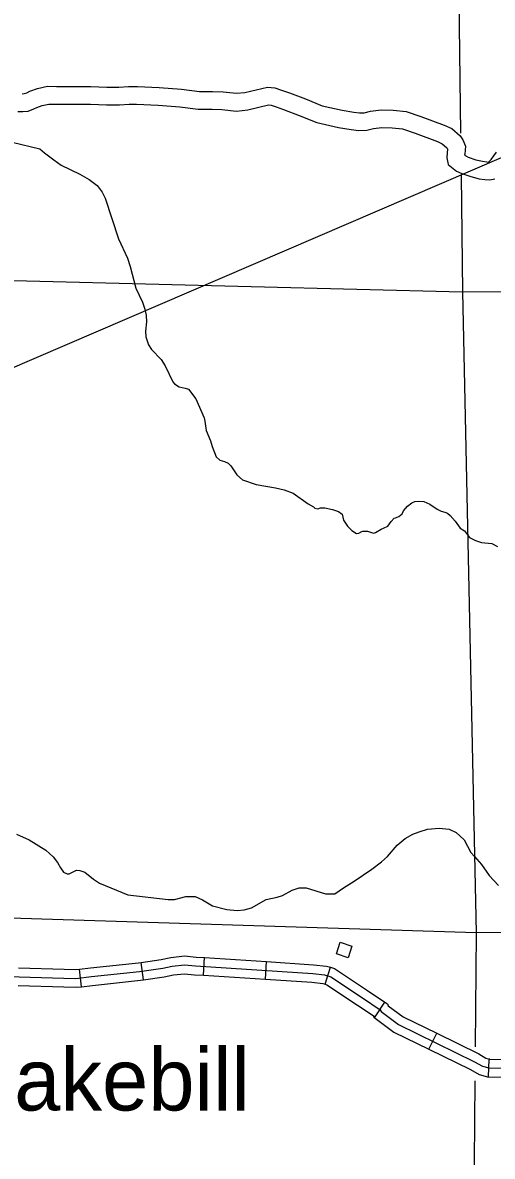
# Model space of a CAD drawing. Extents: x 1369885 to 1370219, y 379980 to 380218.
# Drawn here: x 1370011.52 to 1370027.38, y 380056.29 to 380094.55 of the extents above; entities that cross this region are included whole.
import ezdxf

# ---------------------------------------------------------------- set-up
doc = ezdxf.new("R2010")
doc.units = 0
for name, color, linetype in [('Level 24', 7, 'Continuous'), ('Level 32', 7, 'Continuous'), ('Level 35', 7, 'Continuous'), ('Level 46', 7, 'Continuous'), ('Level 5', 7, 'Continuous'), ('Level 56', 7, 'Continuous'), ('Page Text', 7, 'Continuous')]:
    doc.layers.add(name, color=color, linetype=linetype)

msp = doc.modelspace()

# ---------------------------------------------------------------- linework, layer by layer
at = {"layer": 'Level 32'}
for p, q in [((1370015.603, 380062.251), (1370015.519, 380062.841)), ((1370017.623, 380062.403), (1370017.661, 380062.999)), ((1370019.719, 380062.269), (1370019.757, 380062.864)), ((1370013.507, 380062.02), (1370013.44, 380062.613)), ((1370021.741, 380062.102), (1370021.915, 380062.673)), ((1370023.422, 380061.001), (1370023.754, 380061.496)), ((1370025.239, 380059.91), (1370025.502, 380060.446)), ((1370027.257, 380058.981), (1370027.269, 380059.577))]:
    msp.add_line(p, q, dxfattribs=at)
for points in [[(1370013.44, 380062.613), (1370013.813, 380062.655), (1370015.429, 380062.829), (1370015.519, 380062.841)], [(1370015.519, 380062.841), (1370016.197, 380062.937), (1370016.521, 380063.005), (1370016.988, 380063.057), (1370017.378, 380063.017), (1370017.661, 380062.999)], [(1370017.661, 380062.999), (1370019.757, 380062.864)], [(1370019.757, 380062.864), (1370021.341, 380062.762), (1370021.78, 380062.714), (1370021.915, 380062.673)], [(1370011.018, 380062.364), (1370012.915, 380062.308), (1370013.317, 380062.299), (1370013.846, 380062.359), (1370015.466, 380062.533), (1370016.249, 380062.643)], [(1370011.384, 380062.652), (1370012.923, 380062.606), (1370013.304, 380062.598), (1370013.44, 380062.613)], [(1370015.603, 380062.251), (1370016.3, 380062.349), (1370016.616, 380062.415), (1370016.99, 380062.457), (1370017.329, 380062.422), (1370017.623, 380062.403)], [(1370016.249, 380062.643), (1370016.569, 380062.71), (1370016.989, 380062.757), (1370017.353, 380062.72), (1370021.315, 380062.465), (1370021.719, 380062.42), (1370021.926, 380062.357), (1370022.997, 380061.646), (1370023.599, 380061.241), (1370023.626, 380061.178), (1370024.211, 380060.746), (1370026.784, 380059.486), (1370027.053, 380059.333), (1370027.26, 380059.279), (1370029.202, 380059.241), (1370030.244, 380059.213), (1370032.987, 380059.233), (1370034.444, 380059.287), (1370034.646, 380059.278)], [(1370021.915, 380062.673), (1370022.055, 380062.63), (1370023.162, 380061.894), (1370023.754, 380061.496)], [(1370013.507, 380062.02), (1370013.879, 380062.062), (1370015.503, 380062.236), (1370015.603, 380062.251)], [(1370017.623, 380062.403), (1370019.719, 380062.269)], [(1370019.719, 380062.269), (1370021.289, 380062.168), (1370021.659, 380062.127), (1370021.741, 380062.102)], [(1370021.741, 380062.102), (1370021.798, 380062.084), (1370022.831, 380061.398), (1370023.422, 380061.001)], [(1370011.366, 380062.056), (1370012.907, 380062.01), (1370013.33, 380062), (1370013.507, 380062.02)], [(1370023.754, 380061.496), (1370023.839, 380061.439), (1370023.869, 380061.37), (1370024.367, 380061.002), (1370025.502, 380060.446)], [(1370023.36, 380061.043), (1370023.384, 380060.986), (1370024.055, 380060.49), (1370025.239, 380059.91)], [(1370025.502, 380060.446), (1370026.923, 380059.75), (1370027.167, 380059.612), (1370027.301, 380059.576), (1370027.269, 380059.577)], [(1370025.239, 380059.91), (1370026.644, 380059.222), (1370026.94, 380059.054), (1370027.219, 380058.981), (1370027.257, 380058.981)], [(1370027.269, 380059.577), (1370029.209, 380059.54), (1370029.371, 380059.535)], [(1370027.257, 380058.981), (1370029.195, 380058.943), (1370029.355, 380058.939)]]:
    msp.add_lwpolyline(points, dxfattribs=at)
at = {"layer": 'Level 35'}
for points in [[(1370011.164, 380090.524), (1370012.097, 380090.293), (1370012.26, 380090.155), (1370012.572, 380089.92), (1370012.819, 380089.748), (1370013.452, 380089.441), (1370013.764, 380089.255), (1370014.032, 380089.06), (1370014.202, 380088.826), (1370014.303, 380088.633), (1370014.762, 380087.256), (1370015.056, 380086.607), (1370015.156, 380086.319), (1370015.345, 380085.592), (1370015.57, 380085.12), (1370015.648, 380084.879), (1370015.691, 380084.669), (1370015.705, 380084.451), (1370015.667, 380084.139), (1370015.685, 380083.944), (1370015.768, 380083.679), (1370015.872, 380083.519), (1370016.193, 380083.182), (1370016.338, 380082.975), (1370016.593, 380082.433), (1370016.647, 380082.359), (1370016.805, 380082.26), (1370017.008, 380082.222), (1370017.117, 380082.178), (1370017.369, 380081.862), (1370017.651, 380081.213), (1370017.678, 380081.102)], [(1370017.678, 380081.102), (1370017.719, 380080.785), (1370017.865, 380080.438), (1370017.918, 380080.245), (1370018.052, 380079.898), (1370018.183, 380079.786), (1370018.335, 380079.747), (1370018.456, 380079.691), (1370018.554, 380079.594), (1370018.754, 380079.297), (1370018.946, 380079.12), (1370019.403, 380078.97), (1370020.054, 380078.856), (1370020.349, 380078.785), (1370020.655, 380078.673), (1370021.158, 380078.317), (1370021.341, 380078.21), (1370021.391, 380078.169), (1370021.493, 380078.149), (1370021.575, 380078.174), (1370021.722, 380078.174), (1370021.981, 380078.123), (1370022.185, 380078.052), (1370022.307, 380077.966), (1370022.358, 380077.762), (1370022.49, 380077.558), (1370022.632, 380077.411), (1370022.79, 380077.309), (1370022.876, 380077.319), (1370022.979, 380077.385), (1370023.006, 380077.39), (1370023.166, 380077.391), (1370023.366, 380077.329), (1370023.431, 380077.35), (1370023.624, 380077.457), (1370023.711, 380077.488), (1370023.858, 380077.558), (1370023.96, 380077.716), (1370024.067, 380077.828), (1370024.112, 380077.838), (1370024.229, 380077.884), (1370024.331, 380077.981), (1370024.376, 380078.079), (1370024.515, 380078.23), (1370024.668, 380078.345), (1370024.768, 380078.389), (1370024.901, 380078.403), (1370025.063, 380078.387), (1370025.267, 380078.301), (1370025.521, 380078.139), (1370025.658, 380078.072), (1370025.775, 380078.037), (1370025.872, 380077.996), (1370025.953, 380077.915), (1370026.126, 380077.731), (1370026.3, 380077.498), (1370026.438, 380077.398), (1370026.614, 380077.182), (1370026.808, 380077.08), (1370027.021, 380077.009), (1370027.365, 380076.972), (1370027.554, 380076.87)], [(1370011.317, 380067.165), (1370011.743, 380066.979), (1370012.306, 380066.621), (1370012.555, 380066.405), (1370012.7, 380066.21), (1370012.797, 380066.026), (1370012.905, 380065.882), (1370013.022, 380065.825), (1370013.089, 380065.824), (1370013.34, 380065.947), (1370013.451, 380065.942), (1370013.62, 380065.887), (1370013.909, 380065.645), (1370014.112, 380065.508), (1370015.077, 380065.115), (1370016.44, 380064.961), (1370016.651, 380064.967), (1370017.029, 380065.058), (1370017.343, 380065.064), (1370017.596, 380064.956), (1370017.932, 380064.747), (1370018.417, 380064.622), (1370018.768, 380064.585), (1370018.997, 380064.612), (1370019.253, 380064.683), (1370019.749, 380064.957), (1370020.12, 380065.036), (1370020.293, 380065.102), (1370020.621, 380065.279), (1370020.861, 380065.354), (1370021.096, 380065.357)], [(1370021.096, 380065.357), (1370021.743, 380065.151), (1370022.061, 380065.151), (1370022.36, 380065.356), (1370022.714, 380065.582), (1370023.313, 380065.982), (1370023.635, 380066.231), (1370023.844, 380066.417), (1370024.166, 380066.79), (1370024.442, 380067.017), (1370024.699, 380067.161), (1370024.915, 380067.243), (1370025.195, 380067.335), (1370025.581, 380067.365), (1370025.927, 380067.335), (1370026.161, 380067.223), (1370026.435, 380066.978), (1370026.653, 380066.546), (1370026.775, 380066.414), (1370027.021, 380066.146), (1370027.27, 380065.768), (1370027.595, 380065.431)]]:
    msp.add_lwpolyline(points, dxfattribs=at)
at = {"layer": 'Level 46'}
for points in [[(1370011.502, 380092.152), (1370011.575, 380092.158), (1370011.657, 380092.189), (1370011.765, 380092.243), (1370012.017, 380092.331), (1370012.356, 380092.403), (1370012.668, 380092.393), (1370013.231, 380092.402), (1370013.823, 380092.393), (1370014.367, 380092.374), (1370014.764, 380092.374), (1370015.094, 380092.402), (1370015.394, 380092.402)], [(1370015.394, 380092.402), (1370016.133, 380092.364), (1370016.888, 380092.307), (1370017.489, 380092.233), (1370017.931, 380092.233), (1370018.294, 380092.213), (1370018.741, 380092.168), (1370019.026, 380092.2), (1370019.785, 380092.378), (1370020.037, 380092.35), (1370020.263, 380092.274), (1370020.534, 380092.187), (1370021.075, 380091.976), (1370021.63, 380091.75), (1370022.308, 380091.603), (1370022.703, 380091.532), (1370022.896, 380091.507), (1370023.056, 380091.514), (1370023.264, 380091.568), (1370023.626, 380091.607), (1370024.033, 380091.602), (1370024.474, 380091.549), (1370024.969, 380091.384), (1370025.755, 380091.089), (1370026.011, 380090.975), (1370026.291, 380090.733), (1370026.38, 380090.595), (1370026.471, 380090.382), (1370026.448, 380090.118), (1370026.446, 380090.085), (1370026.483, 380090.055), (1370026.57, 380090.018), (1370026.829, 380089.928), (1370027.054, 380089.872), (1370027.2, 380089.852), (1370027.252, 380089.846), (1370027.342, 380089.936), (1370027.527, 380090.18)], [(1370011.356, 380091.556), (1370011.524, 380091.556), (1370011.706, 380091.569), (1370011.897, 380091.642), (1370011.997, 380091.692), (1370012.178, 380091.755), (1370012.41, 380091.805), (1370012.663, 380091.796), (1370013.231, 380091.806), (1370013.808, 380091.796), (1370014.357, 380091.777), (1370014.789, 380091.777), (1370015.119, 380091.806), (1370015.363, 380091.806)], [(1370015.363, 380091.806), (1370016.095, 380091.768), (1370016.829, 380091.713), (1370017.452, 380091.636), (1370017.915, 380091.636), (1370018.249, 380091.618), (1370018.745, 380091.568), (1370019.128, 380091.611), (1370019.821, 380091.774), (1370019.908, 380091.764), (1370020.077, 380091.707), (1370020.334, 380091.625), (1370020.854, 380091.421), (1370021.453, 380091.178), (1370022.191, 380091.018), (1370022.613, 380090.941), (1370022.872, 380090.909), (1370023.145, 380090.921), (1370023.371, 380090.98), (1370023.654, 380091.01), (1370023.994, 380091.006), (1370024.343, 380090.964), (1370024.77, 380090.822), (1370025.529, 380090.536), (1370025.688, 380090.465), (1370025.836, 380090.338), (1370025.851, 380090.315), (1370025.863, 380090.285), (1370025.852, 380090.158), (1370025.844, 380089.986), (1370025.892, 380089.763), (1370026.174, 380089.54), (1370026.353, 380089.462), (1370026.658, 380089.356), (1370026.94, 380089.285), (1370027.128, 380089.259), (1370027.295, 380089.242), (1370027.463, 380089.284)]]:
    msp.add_lwpolyline(points, dxfattribs=at)
at = {"layer": 'Level 5'}
for points in [[(1370026.204, 380098.983), (1370026.308, 380090.821)], [(1370026.327, 380089.389), (1370026.377, 380085.471)], [(1370004.957, 380086.008), (1370026.377, 380085.471)], [(1370026.377, 380085.471), (1370047.527, 380085.517)], [(1370026.377, 380085.471), (1370026.83, 380063.839)], [(1370026.83, 380063.839), (1370005.008, 380064.522)], [(1370026.83, 380063.839), (1370026.797, 380059.993)], [(1370032.901, 380063.878), (1370026.83, 380063.839)], [(1370026.788, 380058.839), (1370026.741, 380053.348)]]:
    msp.add_lwpolyline(points, dxfattribs=at)
at = {"layer": 'Level 56'}
msp.add_lwpolyline([(1370022.119, 380063.124), (1370022.247, 380063.518), (1370022.642, 380063.39), (1370022.514, 380062.996)], close=True, dxfattribs=at)
at = {"layer": 'Page Text'}
msp.add_lwpolyline([(1370049.822, 380099.52), (1369957.219, 380059.71)], dxfattribs=at)

# ---------------------------------------------------------------- texts
at = {"layer": 'Level 24'}
msp.add_text('Brakebill', height=2.1003, dxfattribs=at).set_placement((1370008.426, 380057.841))

doc.saveas('drawing.dxf')
